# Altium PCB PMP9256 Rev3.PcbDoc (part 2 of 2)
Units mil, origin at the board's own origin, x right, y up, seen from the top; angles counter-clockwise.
Board outline 5025 x 2070 mil, 4 copper layers (Top Layer, MidLayer1, MidLayer2, Bottom Layer), stack 90 mil thick; 116 components, 45 nets, 245 pads, 340 vias.
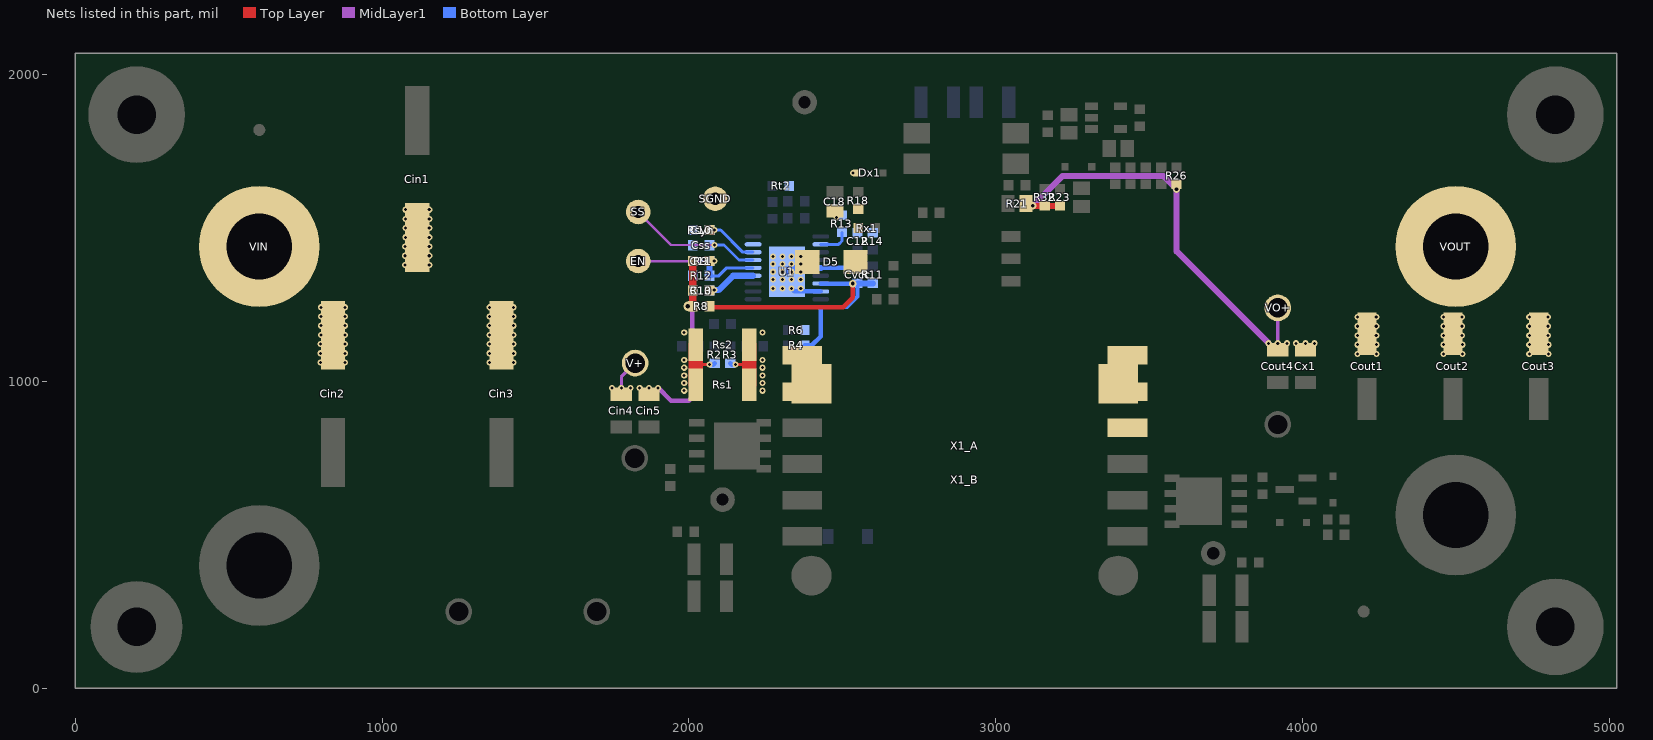
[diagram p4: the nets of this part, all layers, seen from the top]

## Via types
v1: diameter 20, hole 10, Top Layer to Bottom Layer, tented both sides, 258 vias
v2: diameter 20, hole 10, Top Layer to Bottom Layer, 50 vias
v3: diameter 28, hole 10, Top Layer to Bottom Layer, tented top, 24 vias
v4: diameter 24, hole 12, Top Layer to Bottom Layer, tented both sides, 5 vias
v5: diameter 30, hole 15, Top Layer to Bottom Layer, tented both sides, 3 vias

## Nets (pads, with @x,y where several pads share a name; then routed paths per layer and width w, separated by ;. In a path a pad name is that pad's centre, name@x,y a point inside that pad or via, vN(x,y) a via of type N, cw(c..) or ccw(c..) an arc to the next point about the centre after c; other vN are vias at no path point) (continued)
RS-: R3.2 Rs1.2 Rs2.2 X1_A.1 X1_A.2 X1_B.1 | length 181.7
  Top Layer w10: v1(2152,1055) 2196.61,1055
  Top Layer w47: Rs1.2@2196.61,990 2196.61,1055 Rs2.2@2196.61,1120
  Bottom Layer w15: R3.2@2135,1060 R3.2@2140,1055
  other v1: 2240,970 2240,995 2240,1020 2240,1045 2240,1070 2240,1160
SGND: C11.2 C12.2 C13.2 C18.2 Css.2 Cvcc.1 D5.2 Dx1.2 R6.1 R12.1 R13.1 R14.1 Rsyn.1 Rt2.1 SGND.1 U1.9 U1.15 U1.18 U1.21 | length 334.3
  Bottom Layer w15: v1(2335,1302.56) 2343.98,1293.58 U1.18@2430.24,1293.58 ; U1.15@2430.44,1370.56 Cvcc.1@2550,1370.56
  Bottom Layer w20: U1.21@2320,1357.56 2332.8,1370.35 U1.15@2430.24,1370.35 U1.15@2430.44,1370.56
  other v1: 2275,1302.56 2305,1302.56 2365,1302.56 2275,1332.56 2305,1332.56 2335,1332.56 2365,1332.56 2275,1357.56 2305,1357.56 2335,1357.56 2365,1357.56 2275,1382.56 2305,1382.56 2335,1382.56 2365,1382.56 2275,1407.56 2305,1407.56 2335,1407.56 2365,1407.56 2481,1535 2535,1680
SLOPE: R13.2 U1.12 | length 101.9
  Bottom Layer w10: U1.12@2430.24,1447.13 2488.57,1447.13 2499.27,1457.83 R13.2@2499.27,1486.3
SS: Css.1 SS.1 U1.7 | length 456.1
  MidLayer1 w8: SS.1@1834.88,1552.38 1942.31,1444.96 v1(2084,1444.96)
  Bottom Layer w10: Css.1@2067.56,1444.96 v1(2084,1444.96) 2114.97,1444.96 2163.99,1395.94 U1.7@2209.76,1395.94
SYN/RT: C10.1 Rsyn.2 U1.8 | length 168.7
  Bottom Layer w10: Rsyn.2@2070.91,1493.56 2104,1493.56 2176.02,1421.54 U1.8@2209.76,1421.54
  other v1: 2084,1493.56
SYNC: U1.1
UVLO: C11.1 EN.1 R9.1 R12.2 U1.6 | length 463.5
  MidLayer1 w8: EN.1@1835,1392.56 v1(2083,1392.56)
  Bottom Layer w10: R12.2@2067.56,1344.56 2098,1344.56 2123.8,1370.35 U1.6@2209.76,1370.35 ; C11.1@2067.56,1392.56 v1(2083,1392.56)
  Bottom Layer w20: R12.2@2067.56,1344.56 C11.1@2067.56,1391.75
V+: Cin1.1 Cin2.1 Cin3.1 Cin4.1 Cin5.1 R2.2 R8.1 R9.2 R10.2 Rs1.1 Rs2.1 V+.1 VIN.1 | length 864.6
  Top Layer w10: 2023.39,1055 v1(2068,1055)
  Top Layer w25: R8.1@2012.44,1245 R10.2@2012.44,1296.56 R9.2@2012.44,1392.56
  Top Layer w47: Rs1.1@2023.39,990 2023.39,1055 Rs2.1@2023.39,1120
  MidLayer1 w10: v1(1780,979) 1780,1015 V+.1@1825,1060
  MidLayer1 w15: v1(1900,979) 1942,937 2000,937 2011,948 2011,1231 v5(1997,1245)
  Bottom Layer w15: R2.2@2080,1055 R2.2@2085,1060
  other v1: 1985,970 1750,979 1810,979 1840,979 1870,979 1985,995 1985,1020 1985,1045 800,1061.89 879,1061.89 1350,1061.89 1429,1061.89 1985,1070 800,1091.89 879,1091.89 1350,1091.89 1429,1091.89 800,1121.89 879,1121.89 1350,1121.89 1429,1121.89 801,1151.89 879,1151.89 1351,1151.89 1429,1151.89 1985.07,1160 801,1181.89 879,1181.89 1351,1181.89 1429,1181.89 801,1211.89 879,1211.89 1351,1211.89 1429,1211.89 801,1241.89 879,1241.89 1351,1241.89 1429,1241.89 1075,1380 1154,1380 1075,1410 1154,1410 1075,1440 1154,1440 1076,1470 1154,1470 1076,1500 1154,1500 1076,1530 1154,1530 1076,1560 1154,1560
VCC: Cvcc.2 D5.1 R4.2 R8.2 R11.2 R18.1 Rx1.2 U1.17 U1.20 | length 1034
  Top Layer w15: R8.2@2067.56,1245 2070.16,1242.4 2503.36,1242.4 2534.43,1273.47 v4(2534.43,1319.17)
  Bottom Layer w10: Cvcc.2@2550,1319.17 Cvcc.2@2550,1320
  Bottom Layer w13: U1.20@2430.24,1242.4 2515.84,1242.4 2550,1276.56 Cvcc.2@2550,1319.17
  Bottom Layer w15: R4.2@2377.56,1117.56 2401,1117.56 2430.24,1146.8 U1.20@2430.24,1242.4 ; U1.17@2430.24,1319.17 v4(2534.43,1319.17) Cvcc.2@2550,1319.17
  Bottom Layer w20: Cvcc.2@2550,1320 R11.2@2600,1320
"VIN IC": C13.1 R10.1 U1.5 | length 157.8
  Bottom Layer w20: C13.1@2071.37,1297.89 2097.33,1297.89 2144.2,1344.76 U1.5@2209.76,1344.76
  other v1: 2083,1297.89
VOUT: Cout1.1 Cout2.1 Cout3.1 Cout4.1 Cx1.1 R21.2 R23.2 R26.2 R32.1 VO+.1 VOUT.1 X1_A.10 X1_A.11 X1_A.12 X1_B.4 | length 1383.1
  Top Layer w20: R21.2@3099.53,1580 3107.09,1572.44 R32.1@3160,1572.44 R23.2@3210,1572.44
  MidLayer1 w10: v1(3920,1124.5) VO+.1@3920,1240
  MidLayer1 w20: v4(3121,1572.44) 3218.56,1670 3547,1670 v4(3590,1627) 3590,1424.5 v1(3890,1124.5)
  other v1: 4180,1090 4242,1090 4460,1090 4522,1090 4740,1090 4802,1090 4180,1120 4242,1120 4460,1120 4522,1120 4740,1120 4802,1120 3950,1124.5 3980,1124.5 4010,1124.5 4040,1124.5 4180,1150 4241,1150 4460,1150 4521,1150 4740,1150 4801,1150 4180,1180 4241,1180 4460,1180 4521,1180 4740,1180 4801,1180 4180,1210 4241,1210 4460,1210 4521,1210 4740,1210 4801,1210
pads on no net: FID1.1 FID2.1 H3. H4. H7. H8. U3.1 U3.2 X2.2 X2.5

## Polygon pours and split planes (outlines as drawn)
PGND on Bottom Layer "Bottom Layer-PGND" (solid, pour order 22): 0,2070 0,0 2895,0 2895,2070
"ISO GND" on Bottom Layer "Bottom Layer-ISOGND" (solid, pour order 24): 5025,0 5025,2070 2905,2070 2905,0
SGND on Bottom Layer "Bottom Layer-SGND" (solid, pour order 23): 2070,1740 2575,1740 2640,1675 2640,1387.56 2400,1147.56 2050,1147.56 1980,1217.56 1980,1649.56
VCC on Top Layer "Top Layer-VCC" (solid, pour order 36): 2570,1580 2530,1580 2530,1470 2500,1440 2500,1320 2510,1310 2520,1300 2550,1300 2570,1300 2590,1320 2590,1450 2570,1470
PGND on Top Layer "Top Layer-PGND" (solid, pour order 33): 2900,2070 2900,1229.76 1765.24,1229.76 1275,1720 525,1720 360,1555 360,900 2055,900 2055,0 0,0 0,2070
V+ on Top Layer "Top Layer-VIN" (solid, pour order 26): 371,1551 371,910 2100,910 2100,1220 1760,1220 1270,1710 530,1710
VOUT on Top Layer "Top Layer-VOUT" (solid, pour order 29): 2905,1220 2905,795 3755,795 3755,925 3885,1055 4860.17,1055 4860.17,1529.83 4679.7,1710 4050,1710 3560,1220
"ISO GND" on Top Layer "Top Layer-ISGND" (solid, pour order 35): 2905,2070 2905,1230.12 3553.12,1230.12 4043,1720 4685,1720 4870,1535 4870,1045 3890,1045 3765,920 3765,0 5025,0 5025,2070
RS- on Top Layer "Top Layer-RS-" (solid, pour order 27): 2900,1220 2900,910 2120,910 2120,1220
Q2-D on Top Layer "Top Layer-Q2-D" (solid, pour order 31): 3755,785 2905,785 2905,0 3755,0
Q1-D on Top Layer "Top Layer-Q1-D" (solid, pour order 30): 2895,900 2065,900 2065,0 2895,0
PGND on MidLayer2 "MidLayer2-PGND" (solid, pour order 20): 0,0 0,2070 2895,2070 2895,0
"ISO GND" on MidLayer2 "MidLayer2-ISOGND" (solid, pour order 21): 2905,0 5025,0 5025,2070 2905,2070
PGND on MidLayer1 "MidLayer1-PGND" (solid, pour order 32): 2900,2070 2900,1229.76 1765.24,1229.76 1275,1720 525,1720 360,1555 360,900 2895,900 2895,0 0,0 0,2070
V+ on MidLayer1 "MidLayer1-VIN" (solid, pour order 25): 370,1550 370,910 2895,910 2895,1220 1760,1220 1270,1710 530,1710
VOUT on MidLayer1 "MidLayer1-VOUT" (solid, pour order 28): 2905,1220 2905,795 3755,795 3755,925 3885,1055 4860.17,1055 4860.17,1529.83 4679.7,1710 4050,1710 3560,1220
"ISO GND" on MidLayer1 "MidLayer1-ISGND" (solid, pour order 34): 2905,2070 2905,1230.12 3553.12,1230.12 4043,1720 4685,1720 4870,1535 4870,1045 3890,1045 3765,920 3765,785 2905,785 2905,0 5025,0 5025,2070

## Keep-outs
Keep-Out Layer:
  the board outline again, w10
  text ".Layer_Name" at -473,-1568.49 h60

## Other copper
Top Layer:
  pour cut-out: 360,910 360,900 2055,900 2055,0 2065,0 2065,900 2895,900 2895,0 2905,0 2905,785 3755,785 3755,0 3765,0 3765,920 3890,1045 4870,1045 4870,1055.02 3885,1055 3755,925 3755,795 2905,795 2905,1220 2895,1220 2895,910 2120,910 2120,1220 3560,1220 4050,1710 4679.7,1710 4860.17,1529.83 4860,1055 4870,1055 4870,1535 4685,1720 4043,1720 3553.43,1230.43 2905,1230 2905,2070 2895,2070 2895,1230.23 2110,1230 1765,1230 1275,1720 525,1720 360,1555 360,910 370,910 370,1550 530,1710 1270,1710 1760,1220 2100,1220 2100,910
  pour cut-out: 2068,1071.63 2068,1038.37 2046,1038.37 2046,1071.63
  pour cut-out: 2152,1038.37 2152,1071.63 2174,1071.63 2174,1038.37
  pour cut-out: 3870.07,860 ccw(c3920,860) 3920,810.07 ccw(c3920,860) 3969.93,860 ccw(c3920,860) 3920,909.93 ccw(c3920,860)
  pour cut-out: 3870.07,1240 ccw(c3920,1240) 3920,1190.07 ccw(c3920,1240) 3969.93,1240 ccw(c3920,1240) 3920,1289.93 ccw(c3920,1240)
  pour cut-out: 1774.07,750 ccw(c1824,750) 1824,700.07 ccw(c1824,750) 1873.93,750 ccw(c1824,750) 1824,799.93 ccw(c1824,750)
  pour cut-out: 1775.07,1060 ccw(c1825,1060) 1825,1010.07 ccw(c1825,1060) 1874.93,1060 ccw(c1825,1060) 1825,1109.93 ccw(c1825,1060)
  pour cut-out: 2051.69,1055 ccw(c2068,1055) 2068,1038.69 ccw(c2068,1055) 2084.31,1055 ccw(c2068,1055) 2068,1071.31 ccw(c2068,1055)
  pour cut-out: 2135.69,1055 ccw(c2152,1055) 2152,1038.69 ccw(c2152,1055) 2168.31,1055 ccw(c2152,1055) 2152,1071.31 ccw(c2152,1055)
  text ".Layer_Name" at -473,-1568.49 h60
MidLayer1:
  pour cut-out: 2905,2070 2905,0 2895,0 2895,2070
  pour cut-out: 360,910 360,900 2895,900 2895,0 2905,0 2905,785 3765,785 3765,920 3890,1045 4870,1045 4870,1055.02 3885,1055 3755,925 3755,795 2905,795 2905,1220 3560,1220 4050,1710 4679.7,1710 4860.17,1529.83 4860,1055 4870,1055 4870,1535 4685,1720 4043,1720 3553,1230 1765,1230 1275,1720 525,1720 360,1555 360,910 370,910 370,1550 530,1710 1270,1710 1760,1220 2895,1220 2895,910
  pour cut-out: 3870.07,860 ccw(c3920,860) 3920,810.07 ccw(c3920,860) 3969.93,860 ccw(c3920,860) 3920,909.93 ccw(c3920,860)
  pour cut-out: 3870.07,1240 ccw(c3920,1240) 3920,1190.07 ccw(c3920,1240) 3969.93,1240 ccw(c3920,1240) 3920,1289.93 ccw(c3920,1240)
  pour cut-out: 1774.07,750 ccw(c1824,750) 1824,700.07 ccw(c1824,750) 1873.93,750 ccw(c1824,750) 1824,799.93 ccw(c1824,750)
  pour cut-out: 1763.69,831 ccw(c1780,831) 1780,814.69 ccw(c1780,831) 1796.31,831 ccw(c1780,831) 1780,847.31 ccw(c1780,831)
  pour cut-out: 1763.69,979 ccw(c1780,979) 1780,962.69 ccw(c1780,979) 1796.31,979 ccw(c1780,979) 1780,995.31 ccw(c1780,979)
  pour cut-out: 1775.07,1060 ccw(c1825,1060) 1825,1010.07 ccw(c1825,1060) 1874.93,1060 ccw(c1825,1060) 1825,1109.93 ccw(c1825,1060)
  pour cut-out: 3936.31,974.5 ccw(c3920,974.5) 3920,990.81 ccw(c3920,974.5) 3903.69,974.5 ccw(c3920,974.5) 3920,958.19 ccw(c3920,974.5)
  pour cut-out: 3936.11,1124.5 ccw(c3920,1124.5) 3920,1140.61 ccw(c3920,1124.5) 3903.89,1124.5 ccw(c3920,1124.5) 3920,1108.39 ccw(c3920,1124.5)
  pour cut-out: 1883.37,979 ccw(c1900,979) 1900,962.37 ccw(c1900,979) 1916.63,979 ccw(c1900,979) 1900,995.63 ccw(c1900,979)
  pour cut-out: 2051.69,1055 ccw(c2068,1055) 2068,1038.69 ccw(c2068,1055) 2084.31,1055 ccw(c2068,1055) 2068,1071.31 ccw(c2068,1055)
MidLayer2:
  rectangle net SGND: 2258,1265.16 2388,1452.16
  pour cut-out: 2895,2070 2905,2070 2905,0 2895,0
Bottom Layer:
  rectangle net NetC26_1: 2840,1857 2960,1962
  pour cut-out: 2345,1515.56 2397.43,1515.56 2397.43,1415.56 2386,1415.56 2386,1506.83 2345,1506.83
  pour cut-out: 1970,1655 1970,1212.56 2045.14,1137.42 2400,1137.62 2400,1147.56 2050,1147.56 1980,1217.56 1980,1650 2070,1740 2575,1740 2640,1675 2640,1387.56 2400,1147.56 2400,1137.63 2650,1383.32 2650,1680 2580,1750 2065,1750
  pour cut-out: 2895,2070 2905,2070 2905,0 2895,0
  text ".Layer_Name" at -473,-1568.49 h60

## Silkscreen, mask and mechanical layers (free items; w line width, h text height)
Top Overlay:
  text ".CopyrightYear" at 4111,84.52 h60
  text "TI" at 4387,84.52 h60
  text "©" at 3994,81 h105
  text "LM5122" at 2533,63 h60
  text "FlyBack" at 2933,63 h60
  text ".Layer_Name" at -473,-1568.49 h60
Bottom Overlay:
  rectangle: 2478,829 2778,929
  text "PMP9256" at 3444,839 h60
  text "-" at 2843,828.5 h60
  text "E1" at 2877,708 h60
  text "UL94V-0" at 119,495 h60 r270
  text "MADE IN U.S." at 4550,83 h60
  text ".Layer_Name" at -473,-1568.49 h60
Top Paste:
  text ".Layer_Name" at -473,-1568.49 h60
Bottom Paste:
  text ".Layer_Name" at -473,-1568.49 h60
Top Solder:
  text ".Layer_Name" at -473,-1568.49 h60
  text ".Layer_Name" at -473,-1568.49 h60
Bottom Solder:
  text ".Layer_Name" at -473,-1568.49 h60
Drill Guide:
  text ".Layer_Name" at -473,-1568.49 h60
M1 Board Outline:
  the board outline again, w10
  text ".Layer_Name" at -473,-1568.49 h60
M2 Board Dimensions:
  rectangle: -1050.5,-995.5 -925.5,-870.5
  rectangle: -925.5,-1120.5 -550.5,-995.5
  lines w7: -1050.5,-995.5 -50.5,-995.5 ; -925.5,-1120.5 -925.5,-870.5 ; -800.5,-1120.5 -800.5,-870.5 ; -550.5,-1120.5 -550.5,-870.5 ; -300.5,-1120.5 -300.5,-870.5 ; -1050.5,-1120.5 -50.5,-1120.5 -50.5,-870.5 -1050.5,-870.5 -1050.5,-1120.5
  lines w10: -1050.5,-1185.5 -1050.5,-1165.5 ; -990.5,-1195.5 -1050.5,-1175.5 ; -990.5,-1155.5 -1050.5,-1175.5 ; -826.42,-1175.5 -1050.5,-1175.5 ; -274.58,-1175.5 -50.5,-1175.5 ; -110.5,-1195.5 -50.5,-1175.5 ; -110.5,-1155.5 -50.5,-1175.5 ; -50.5,-1185.5 -50.5,-1165.5
  text "1000 (mil)" at -816.42,-1211.49 h60
  text ".Layer_Name" at -473,-1568.49 h60
M3 3D STEP Top:
  text ".Layer_Name" at -473,-1568.49 h60
M4 3D STEP Bottom:
  text ".Layer_Name" at -473,-1568.49 h60
M5 Assembly Top:
  lines w10: -1342,-1640.17 5258,-1640.17 ; -1342,-1436.83 5260,-1436.83 ; -1342,-1233.5 -1342,-1843.5 2663,-1843.5 5260,-1843.5 5260,-1233.5 -1341.5,-1233.5 -1341.5,-1843.5 234,-1843.5 ; 1123,-1843.5 1123,-1233.5 ; 2390,-1436.83 2390,-1233.5 ; 3230,-1436.83 3230,-1233.5 ; 3852,-1850 3852,-1647.17
  text "COMPONENTS MARKED 'DNP' SHOULD NOT BE POPULATED." at 103.5,-1028.5 h60
  text "ASSEMBLY VARIANT:" at 103,-1144 h60
  text ".VariantName" at 1139,-1144 h60
  text "PCB VIEWED FROM TOP SIDE" at -1278.5,-1365.67 h60
  text "BOARD #:" at 1198,-1365.67 h60
  text ".PRJ_Number" at 1743.5,-1365.67 h60
  text "REV:" at 2588,-1365.67 h60
  text "E1" at 2879.5,-1365.67 h60
  text "SVN REV:" at 3426,-1365.67 h60
  text ".VersionControl_RevNumber" at 3932,-1365.67 h60
  text "IGNORE ->" at -1278.5,-1568.49 h60
  text "PLOT NAME =" at -1278.5,-1774.34 h60
  text ".plot_File_Name" at -473,-1774.34 h60
  text "GENERATED    :" at 1200,-1774.34 h60
  text ".Print_Date" at 2069.5,-1774.34 h60
  text ".Print_Time" at 2798.5,-1774.34 h60
  text "TEXAS INSTRUMENTS" at 4063,-1774.34 h60
M6 Assembly Bottom:
  lines w10: -1342.5,-1437.33 5259.5,-1437.33 ; -1340.5,-1640.67 5259.5,-1640.67 ; 65.5,-1850.5 65.5,-1647.67 ; 687.5,-1437.33 687.5,-1234 ; 1527.5,-1437.33 1527.5,-1234 ; 2794.5,-1844 2794.5,-1234 ; 3683.5,-1844 5259,-1844 5259,-1234 -1342.5,-1234 -1342.5,-1844 1254.5,-1844 5259.5,-1844 5259.5,-1234
  text "COMPONENTS MARKED 'DNP' SHOULD NOT BE POPULATED." at 5052,-1028 h60
  text ".VariantName" at 4008,-1144 h60
  text "ASSEMBLY VARIANT:" at 5047,-1144 h60
  text ".VersionControl_RevNumber" at -14.5,-1366.17 h60
  text "SVN REV:" at 491.5,-1366.17 h60
  text ".PCB_Rev" at 1038,-1366.17 h60
  text "REV:" at 1329.5,-1366.17 h60
  text ".PRJ_Number" at 2174,-1366.17 h60
  text "BOARD #:" at 2719.5,-1366.17 h60
  text "PCB VIEWED FROM BOTTOM SIDE" at 5196,-1366.17 h60
  text "IGNORE ->" at 1497.85,-1568.49 h60
  text "TEXAS INSTRUMENTS" at -145.5,-1774.84 h60
  text ".Print_Time" at 1119,-1774.84 h60
  text ".Print_Date" at 1848,-1774.84 h60
  text "GENERATED    :" at 2717.5,-1774.84 h60
  text ".plot_File_Name" at 4390.5,-1774.84 h60
  text "PLOT NAME =" at 5196,-1774.84 h60
M9 Title Sheet:
  drawing of 57 lines, arcs and shapes, not listed
  text "1" at -310.16,7326.5 h70
  text "2" at 2185.5,7326.5 h70
  text "3" at 4674.84,7326.5 h70
  text "4" at 7181.51,7326.5 h70
  text "5" at 9680.5,7326.5 h70
  text "6" at 12185.5,7326.5 h70
  text "A" at -1466.5,6183.5 h70
  text "A" at 13333.5,6183.5 h70
  text "B" at -1466.5,3803.5 h70
  text "B" at 13333.5,3803.5 h70
  text "C" at -1466.5,1428.5 h70
  text "C" at 13333.5,1428.5 h70
  text "PROJECT TITLE:" at 10293.5,-432.5 h45
  text ".PRJ_Title" at 10343.5,-565.83 h70
  text "DESIGNED FOR:" at 10293.5,-733.5 h45
  text ".PRJ_Customer" at 10343.5,-873.5 h70
  text "D" at -1466.5,-941.5 h70
  text "D" at 13333.5,-941.5 h70
  text "FILE NAME:" at 10293.5,-1033.5 h45
  text ".PCB_File_Name_No_Path" at 10343.5,-1153.5 h70
  text "Texas Instruments (TI) and/or its licensors do not warrant the accuracy or completeness of this specification" at 5324,-1315.34 h45
  text "ENGINEER:" at 10293.5,-1323.5 h45
  text "LAYOUT BY:" at 11798.5,-1323.5 h45
  text "or any information contained therein. TI and/or its licensors do not warrant that this design will meet" at 5279.01,-1428 h45
  text "David Baba" at 10343.5,-1478.49 h70
  text "Jacen Schaedler" at 11849,-1478.49 h70
  text "the specifications, will be suitable for your application or fit for any particular purpose, or will operate in" at 5279.01,-1540.67 h45
  text ".Layer_Name" at -473,-1568.49 h60
  text "ALTIUM DESIGNER VERSION:" at 11798.5,-1633.5 h45
  text "an implementation. TI and/or its licensors do not warrant that the design is production worthy. You should" at 5279.01,-1653.33 h45
  text "completely validate and test your design implementation to confirm the system functionality for your application." at 5324,-1766 h45
  text ".print_Scale" at 10343.5,-1766.83 h70
  text ".Application_BuildNumber" at 11849,-1766.83 h70
  text "1" at -310.16,-1973.5 h70
  text "2" at 2185.5,-1973.5 h70
  text "3" at 4674.84,-1973.5 h70
  text "4" at 7181.51,-1973.5 h70
  text "5" at 9680.5,-1973.5 h70
  text "6" at 12185.5,-1973.5 h70
M10 Fab Notes:
  drawing of 207 lines, arcs and shapes, not listed
  text "DESIGN INFORMATION" at 11331.02,6100 h60
  text "(REFER ALSO ARRAY/PANEL PROFILING INFORMATION)" at 10969.46,5938.29 h60
  text "BOARD SIZE" at 10283.46,5934 h60
  text "3170MIL" at 10745.78,5806.18 h60
  text "X" at 11251.46,5806.18 h60
  text "4000MIL" at 11482.78,5806.18 h60
  text "Number of Layers :" at 10686.46,5609 h60
  text "4" at 11781.27,5599 h60
  text "MIN. TRACK WIDTH:" at 10686.46,5470 h60
  text "6" at 11782.7,5470 h60
  text "MIL" at 11937.46,5470 h60
  text "MIN. CLEARANCE:" at 10686.46,5338 h60
  text "8" at 11782.7,5338 h60
  text "MIL" at 11937.46,5338 h60
  text "MIN. VIA PAD SIZE:" at 10686.46,5206 h60
  text "10" at 11752.71,5206 h60
  text "MIL" at 11937.46,5206 h60
  text "0.05mm (2MIL)" at 11381.46,5064.29 h60
  text "MINIMUM ANNULAR RING" at 10357.23,5060 h60
  text "EXTERNAL" at 12089.46,5060 h60
  text "PER" at 10557.23,4942 h60
  text "IPC-D-275 CLASS 2 LEVEL C" at 10777.23,4942 h60
  text "MIL, HOLES" at 12265.46,4829.71 h60
  text "+/-" at 11873,4829 h60
  text "+/-" at 12727,4829 h60
  text "REGISTRATION TOLERANCES:" at 10357.23,4824 h60
  text "METAL" at 11557,4824 h60
  text "5" at 12133.2,4824 h60
  text "3" at 12966.2,4824 h60
  text "MIL" at 13082.46,4824 h60
  text "MATERIAL:" at 10282.46,4614.54 h60
  text "FR-4 High Tg" at 11268.9,4474.21 h60
  text "FR-4" at 10743.46,4465.64 h60
  text "OTHER" at 12191.46,4465.64 h60
  text "X" at 10550,4465 h60
  text "62 MIL (1.6mm) +/-10%" at 11023.56,4302.92 h60
  text "THICKNESS:" at 10357.23,4298.64 h60
  text "X" at 10895.4,4298.64 h60
  text "OTHER" at 12308.46,4298.64 h60
  text "TOLERANCE:" at 10357.23,4140.64 h60
  text "X" at 11196.53,4140.64 h60
  text "ANSI IPC-6012 TYPE 3 CLASS 2" at 11383.48,4140.64 h60
  text "OTHER +/-" at 11383.46,3984.64 h60
  text "BOW & TWIST:" at 10357.23,3827.64 h60
  text "X" at 11196.53,3827.64 h60
  text "ANSI IPC-6012 TYPE 3 CLASS 2" at 11383.48,3827.64 h60
  text "OTHER +/-" at 11383.46,3669.13 h60
  text "COPPER THICKNESS (FINISHED):" at 10282.46,3533.64 h60
  text "1.4MIL (1oz)" at 11162.46,3380.92 h60
  text "2MIL (1.4oz)" at 11929.46,3380.92 h60
  text "2.8MIL (2oz)" at 12656.46,3380.92 h60
  text "OUTER:" at 10639.46,3376.64 h60
  text "X" at 11034,3376 h60
  text "1.4MIL (1oz)" at 11162.46,3223.92 h60
  text "2.8MIL (2oz)" at 11929.46,3223.92 h60
  text "N/A" at 12656,3224.29 h60
  text "INNER SIGNAL:" at 10350.38,3219.64 h60
  text "X" at 11035.42,3219.64 h60
  text "DRILLING:" at 10282.46,3080.64 h60
  text "REFERENCE:" at 10357.23,2963.64 h60
  text "X" at 11005.46,2963.64 h60
  text "AS SHOWN" at 11192.46,2963.64 h60
  text "X" at 11906.46,2963.64 h60
  text "NC_DRILL FILES" at 12043.46,2963.64 h60
  text "PTH MIN COPPER THICKNESS:" at 10357.23,2805.64 h60
  text "X" at 11707.46,2805.64 h60
  text "1MIL" at 11844.46,2805.64 h60
  text "OTHER" at 12341.46,2805.64 h60
  text "BOARD FINISH:" at 10282.46,2646.64 h60
  text "SILKSCREEN:" at 10437.68,2528.64 h60
  text "X" at 11386.46,2528.64 h60
  text "TOP" at 11512.46,2528.64 h60
  text "X" at 11896.46,2528.64 h60
  text "BOTTOM" at 12023.46,2528.64 h60
  text "SILKSCREEN COLOR:" at 10437.68,2361.64 h60
  text "X" at 11385.42,2361.64 h60
  text "WHITE" at 11512.46,2361.64 h60
  text "OTHER" at 12023.46,2361.64 h60
  text "SOLDER RESIST COLOR:" at 10437.68,2191.64 h60
  text "X" at 11005.42,2032.44 h60
  text "GREEN" at 11132.46,2032.44 h60
  text "BLUE" at 11723.46,2032.44 h60
  text "OTHER" at 12261.46,2032.44 h60
  text "IMMERSION GOLD (ENIG)" at 11343.46,1843.92 h60
  text "SURFACE FINISH:" at 10282.46,1839.64 h60
  text "IMM. TIN/SILVER OR EQUIV" at 10612,1682.64 h60
  text "OTHER" at 12043.46,1682.64 h60
  text "X" at 10440,1680 h60
  text "X" at 11155,1505 h60
  text "ARRAY/PANEL:" at 10282.46,1503.64 h60
  text "CUT AND TRIM PER MECH LAYER 1" at 11343.46,1499.35 h60
  text "N.C. ROUTE" at 11343.46,1347.64 h60
  text "V. SCORE" at 12209.46,1347.64 h60
  text "CERTIFICATION:" at 10282.46,1210.64 h60
  text "MATERIALS AND WORKMANSHIP FOR ALL PCBS" at 11007.46,1210.64 h60
  text "TO MEET OR EXCEED THE REQUIREMENTS OF:" at 11007.46,1112.64 h60
  text "X" at 10633.96,976.13 h60
  text "ANSI IPC-A-600F CLASS ->" at 10772.96,976.13 h60
  text "X" at 12412.02,976.13 h60
  text "2" at 12530.96,976.14 h60
  text "1" at 12215.96,974.64 h60
  text "3" at 12884.96,974.64 h60
  text "X" at 10636.02,816.64 h60
  text "UL 94V-0" at 10772.96,816.64 h60
  text "X" at 11448.02,816.64 h60
  text "RoHS" at 11584.96,816.64 h60
  text "OTHER" at 12229.36,816.64 h60
  text "PER ORDER" at 12626.42,816.64 h60
  text "ADDITIONAL REQUIREMENTS:" at 10282.46,675.64 h60
  text "MICROSECTION:" at 10357.23,560.64 h60
  text "YES" at 11262.96,560.64 h60
  text "REQUIRED" at 12124.46,404.49 h60
  text "BARE BOARD ELEC. TEST:" at 10357.23,401.64 h60
  text "NONE" at 11662.96,401.64 h60
  text "PER ORDER" at 12716.46,401.64 h60
  text "X" at 11531.5,395 h60
  text "MANUFACTURER'S ID/LOGO:" at 10357.23,244.64 h60
  text "RAIL" at 11822.96,240.35 h60
  text "METAL" at 12314.77,240.35 h60
  text "SILK" at 12826.46,240.35 h60
  text "X" at 12685,235 h60
  text ".Layer_Name" at -473,-1568.49 h60
M11 Gerber Information:
  lines w10: -1342,-1640.17 5258,-1640.17 ; -1342,-1436.83 5260,-1436.83 ; -1342,-1233.5 -1342,-1843.5 2663,-1843.5 5260,-1843.5 5260,-1233.5 -1341.5,-1233.5 -1341.5,-1843.5 234,-1843.5 ; 1123,-1843.5 1123,-1233.5 ; 2390,-1436.83 2390,-1233.5 ; 3230,-1436.83 3230,-1233.5 ; 3852,-1850 3852,-1647.17
  text "ALL ARTWORK VIEWED FROM TOP SIDE" at -1278.5,-1365.67 h60
  text "BOARD #:" at 1198,-1365.67 h60
  text ".PRJ_Number" at 1743.5,-1365.67 h60
  text "REV:" at 2588,-1365.67 h60
  text "E1" at 2879.5,-1365.67 h60
  text "SVN REV:" at 3426,-1365.67 h60
  text ".VersionControl_RevNumber" at 3932,-1365.67 h60
  text "LAYER NAME =" at -1278.5,-1568.49 h60
  text "PLOT NAME =" at -1278.5,-1774.34 h60
  text ".plot_File_Name" at -473,-1774.34 h60
  text "GENERATED    :" at 1200,-1774.34 h60
  text ".Print_Date" at 2069.5,-1774.34 h60
  text ".Print_Time" at 2798.5,-1774.34 h60
  text "TEXAS INSTRUMENTS" at 4063,-1774.34 h60
M12 Stackup:
  lines w11: 6110,5779.25 10115,5779.25 ; 6110,5978.85 10115,5978.85 ; 6050,4544 ccw(c6114,4544) 6114,4480 10111,4480 ccw(c10111,4544) 10175,4544 10175,6141 ccw(c10111,6141) 10111,6205 6114,6205 ccw(c6114,6141) 6050,6141 6050,4544
  text "Layer Stack Up Detail for: PMP9256.PcbDoc" at 6110,6028.62 h86
  text "Layer" at 6110,5904.35 h46
  text "Gerber" at 7530.65,5904.35 h46
  text "Copper" at 8336.16,5904.35 h46
  text "Dielectric" at 9216.78,5904.35 h46
  text "Name" at 6110,5812.35 h46
  text "Document" at 7530.65,5812.35 h46
  text "Thickness" at 8336.16,5812.35 h46
  text "Material" at 9216.78,5812.35 h46
  text "Top Solder Mask" at 6110,5682.6 h64
  text "(.GTS)" at 7530.65,5682.6 h64
  text "Solder Resist" at 9216.78,5682.6 h64
  text "Top Layer" at 6110,5500.31 h64
  text "(.GTL)" at 7530.65,5500.31 h64
  text "1.4mil" at 8336.16,5500.31 h64
  text "FR-4" at 9216.78,5409.17 h64
  text "MidLayer1" at 6110,5318.02 h64
  text "(.G1)" at 7530.65,5318.02 h64
  text "1.4mil" at 8336.16,5318.02 h64
  text "FR-4" at 9216.78,5226.88 h64
  text "MidLayer2" at 6110,5135.73 h64
  text "(.G2)" at 7530.65,5135.73 h64
  text "1.4mil" at 8336.16,5135.73 h64
  text "FR-4" at 9216.78,5044.58 h64
  text "Bottom Layer" at 6110,4953.44 h64
  text "(.GBL)" at 7530.65,4953.44 h64
  text "1.4mil" at 8336.16,4953.44 h64
  text "Bottom Solder Mask" at 6110,4771.15 h64
  text "(.GBS)" at 7530.65,4771.15 h64
  text "Solder Resist" at 9216.78,4771.15 h64
  text ".Layer_Name" at -473,-1568.49 h60
M13 Component Bodies Top:
  text ".Layer_Name" at -473,-1568.49 h60
M14 Component Bodies Bottom:
  text ".Layer_Name" at -473,-1568.49 h60
M15 Courtyards Top:
  text ".Layer_Name" at -473,-1568.49 h60
M16 Courtyards Bottom:
  text ".Layer_Name" at -473,-1568.49 h60
Drill Drawing:
  text ".Layer_Name" at -473,-1568.49 h60

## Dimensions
0,0 to 5025,0 on M2 Board Dimensions
0,0 to 0,2070 on M2 Board Dimensions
